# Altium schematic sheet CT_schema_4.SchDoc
size 313 x 185 mm
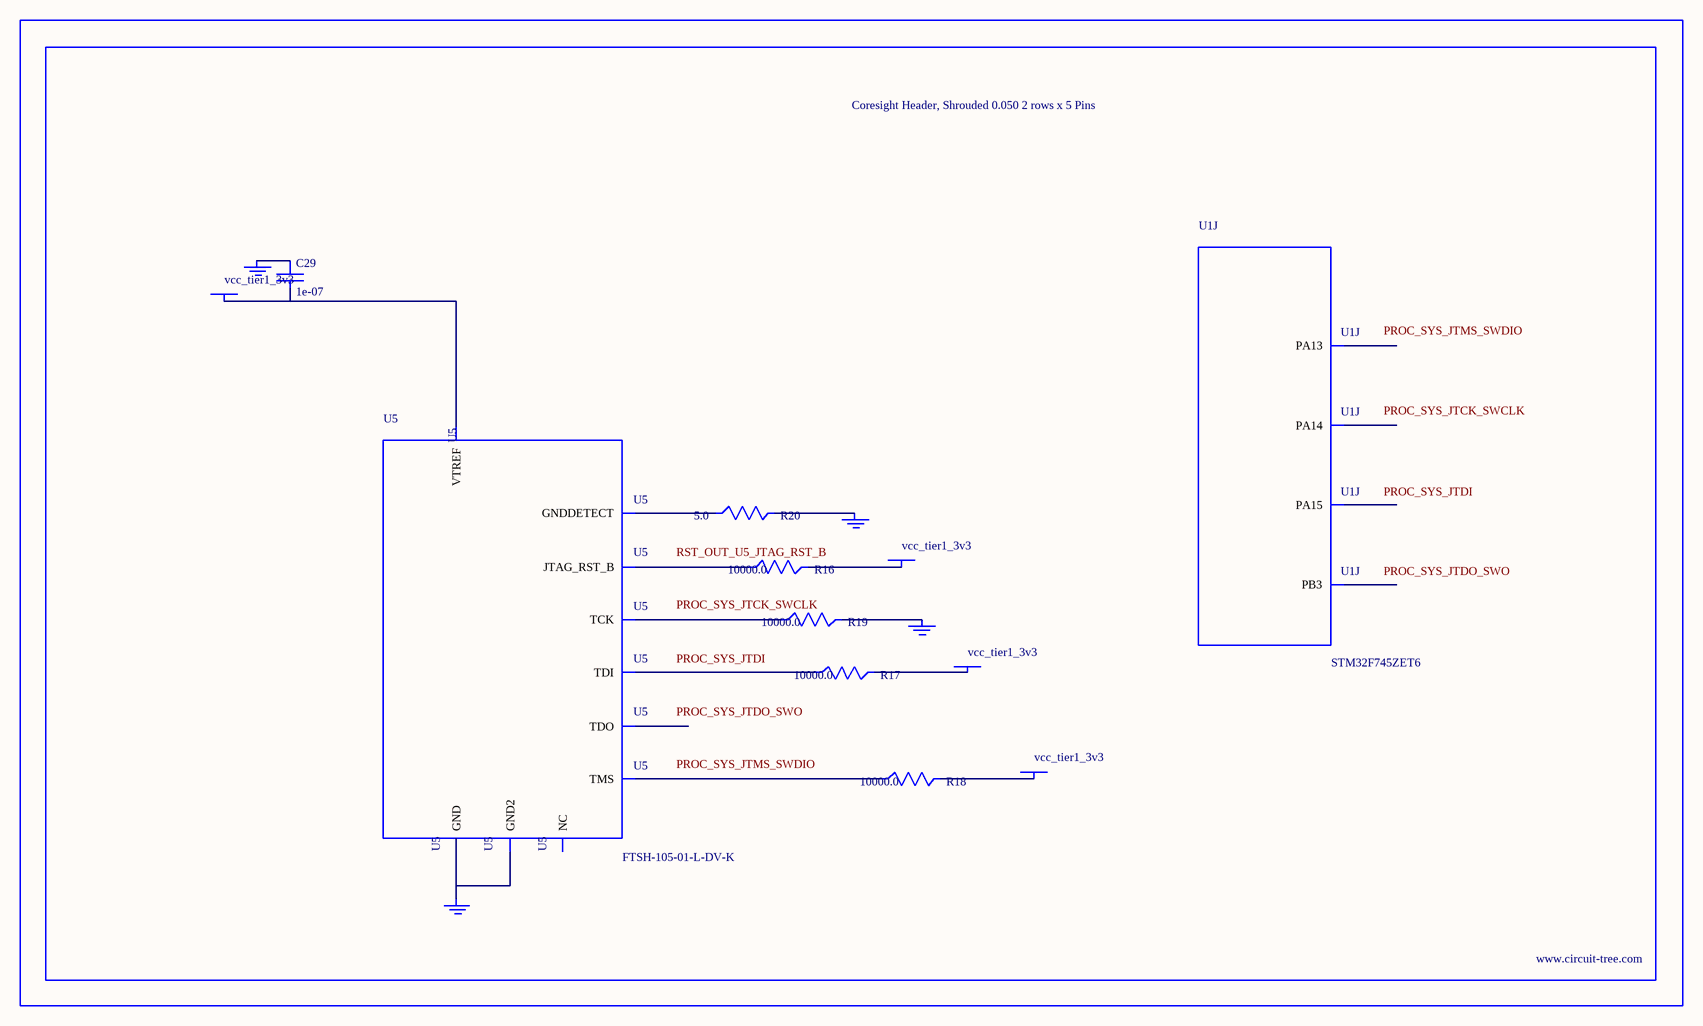
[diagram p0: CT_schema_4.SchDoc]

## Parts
BORDER3  (no value)
C29  1e-07  [C0402]
GND_INSTANCE_3_0  (no value)
GND_INSTANCE_3_1  (no value)
GND_INSTANCE_3_2  (no value)
GND_INSTANCE_3_3  (no value)
POWER_INSTANCE_3_0  vcc_tier1_3v3
POWER_INSTANCE_3_1  vcc_tier1_3v3
POWER_INSTANCE_3_2  vcc_tier1_3v3
POWER_INSTANCE_3_3  vcc_tier1_3v3
R16  10000.0  [R0603]
R17  10000.0  [R0603]
R18  10000.0  [R0603]
R19  10000.0  [R0603]
R20  5.0  [R0603]
U1  STM32F745ZET6  [LQFP144]  (part J of 12)
U5  FTSH-105-01-L-DV-K  [SAMTEC_FTSH-105-01-L-DV-K]

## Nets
NetC29_1: C29.1 GND_INSTANCE_3_0.0(GND)
NetC29_2: C29.2 POWER_INSTANCE_3_0.0(PWR) U5.1(VTREF)
NetGND_INSTANCE_3_1_0: GND_INSTANCE_3_1.0(GND) R19.2
NetGND_INSTANCE_3_2_0: GND_INSTANCE_3_2.0(GND) R20.2
NetGND_INSTANCE_3_3_0: GND_INSTANCE_3_3.0(GND) U5.3(GND) U5.5(GND2)
NetPOWER_INSTANCE_3_1_0: POWER_INSTANCE_3_1.0(PWR) R18.2
NetPOWER_INSTANCE_3_2_0: POWER_INSTANCE_3_2.0(PWR) R17.2
NetPOWER_INSTANCE_3_3_0: POWER_INSTANCE_3_3.0(PWR) R16.2
NetR16_1: R16.1 U5.10(JTAG_RST_B)
NetR17_1: R17.1 U5.8(TDI)
NetR18_1: R18.1 U5.2(TMS)
NetR19_1: R19.1 U5.4(TCK)
NetR20_1: R20.1 U5.9(GNDDETECT)

Not connected (* = marked no-connect by the designer): U1 105(PA13) 109(PA14) 110(PA15) 133(PB3); U5 6(TDO) 7(NC)

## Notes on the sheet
- Labels drawn without touching a wire or pin: PROC_SYS_JTCK_SWCLK, PROC_SYS_JTDI, PROC_SYS_JTDO_SWO, PROC_SYS_JTMS_SWDIO, RST_OUT_U5_JTAG_RST_B

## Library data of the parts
BORDER3 = BORDER_PAGE3
C29 = C0402C104K3RACTU
GND_INSTANCE_3_0-GND_INSTANCE_3_3 = GND
POWER_INSTANCE_3_0-POWER_INSTANCE_3_3 = PWR
R16-R19 = RC0603JR-0710KL
R20 = ERJ-3GEYJ5R1V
